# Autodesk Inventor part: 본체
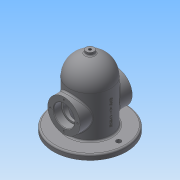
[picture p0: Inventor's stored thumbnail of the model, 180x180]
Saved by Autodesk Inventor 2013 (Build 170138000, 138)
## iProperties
Created: 2019-11
Part Number: 본체
Material: 일반
Document SubType Name: Modeling
Designer: Administrator
Density: 1 g/cm^3
Author: Administrator
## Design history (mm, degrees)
sketch "스케치1"
  geometry: L1 (0, 0)-(0, 130); L2 (0, 0)-(-40, 0); L3 (-40, 0)-(-40, 90); L4 (-40, 90)-(0, 90); A1 r 40 centre (0, 90) between (0, 130) and (0, 50); A2 r 40 centre (0, 90) between (0, 50) and (0, 130)
  constraints: 8 end point, 5 point on circle, 3 perpendicular, 2 centre point, 2 point on line, 1 coincident, 1 vertical
  dimensions: "d1" = 80 diameter of L3 L1; "d22" = 90 distance of L2.end L3.end
revolve "회전1" sketch "스케치1" stored, may be unused: angle "d2" = 90 deg
feature "쉘1" dims "d3" = 10
sketch "스케치2"
  geometry: C1 r 40 at (0, 0) reference; C2 r 70 at (0, 0)
  constraints: 1 centre point, 1 coincident
  dimensions: "d4" = 140 diameter of C2
extrude "돌출1" join sketch "스케치2" distance "d5" = 10; taper "d6" = 0 deg
node "작업 평면1"
sketch "스케치3"
  geometry: L1 (-48.99, 0)-(-48.99, 10) reference; L2 (-48.99, 10)-(48.99, 10) reference; L3 (48.99, 10)-(48.99, 0) reference; L4 (48.99, 0)-(-48.99, 0) reference; C1 r 31 at (0, 50); 2 further points
  constraints: 1 centre point, 1 midpoint, 1 vertical alignment
  dimensions: "d8" = 62 diameter of C1; "d9" = 50 distance from line of L4 C1.centre
extrude "돌출2" join sketch "스케치3" stored distance "d10" = 10; taper "d11" = 0 deg
sketch "스케치4"
  geometry: C1 r 31 at (0, 0) reference; C2 r 20 at (0, 0); 1 further point
  constraints: 1 centre point, 1 coincident
  dimensions: "d12" = 40 diameter of C2
extrude "돌출3" cut sketch "스케치4" distance "d13" = 15; taper "d14" = 0 deg
sketch "스케치5"
  geometry: C1 r 20 at (0, 0) reference; C2 r 16.5 at (0, 0); 1 further point
  constraints: 1 centre point, 1 coincident
  dimensions: "d15" = 33 diameter of C2
extrude "돌출4" cut sketch "스케치5" stored distance "d16" = 15; taper "d17" = 0 deg
node "작업 평면2"
sketch "스케치6"
  geometry: C1 r 7.5 at (0, 0); 1 further point
  constraints: 1 centre point, 1 coincident
  dimensions: "d19" = 15 diameter of C1
extrude "돌출5" join sketch "스케치6" stored distance "d20" = 15; taper "d21" = 0 deg
sketch "스케치7" dims "d23" = 52
  geometry: C1 r 31 at (0, 0) reference; 3 further points
  constraints: 2 vertical alignment, 1 coincident, 2 other
hole "구멍1" sketch "스케치7" at (0, 26) diameter "d24" = 3.242; stored, may be unused: countersink angle "d28" = 90 deg, drill point angle "d30" = 118 deg; dims "d25" = 8, "d26" = 4, "d27" = 2, "d29" = 10
sketch "스케치8" dims "d34" = 110
  geometry: C1 r 70 at (0, 0) reference; 2 further points
  constraints: 2 horizontal alignment, 1 coincident, 2 other
hole "구멍2" sketch "스케치8" at (55, 0) diameter "d35" = 9; stored, may be unused: countersink angle "d39" = 90 deg, drill point angle "d41" = 118 deg; dims "d36" = 8, "d37" = 4, "d38" = 2, "d40" = 10
sketch "스케치9"
  geometry: C1 r 7.5 at (0, 0) reference
hole "구멍3" sketch "스케치9" at (0, 0) diameter "d45" = 5.188; stored, may be unused: countersink angle "d49" = 90 deg, drill point angle "d51" = 118 deg; dims "d46" = 8, "d47" = 4, "d48" = 2, "d50" = 27.75
node "작업 평면3"
sketch "스케치10"
  geometry: L1 (70, 0)-(-70, 0) reference; 2 further points
  constraints: 1 vertical alignment, 1 other
  dimensions: "d53" = 50 distance from line of L1 point (0, 50)
feature "엠보싱1" sketch "스케치10" dims "d54" = 0.5, "d55" = 0
chamfer "모따기1" distance "d56" = 1; stored, may be unused: second distance "d57" = 2, angle "d58" = 45 deg
fillet "모깎기1" dims "d59" = 0.3
fillet "모깎기2" dims "d60" = 3
node "솔리드1"
mirror "대칭2"
pattern_circular "원형 패턴1" dims angle "d32" = 360 deg
mirror "대칭3"
pattern_circular "원형 패턴2" dims angle "d43" = 360 deg
node "절단 모서리 투영1"
other parameters: "d18" = -135, "d52" = 54.75
